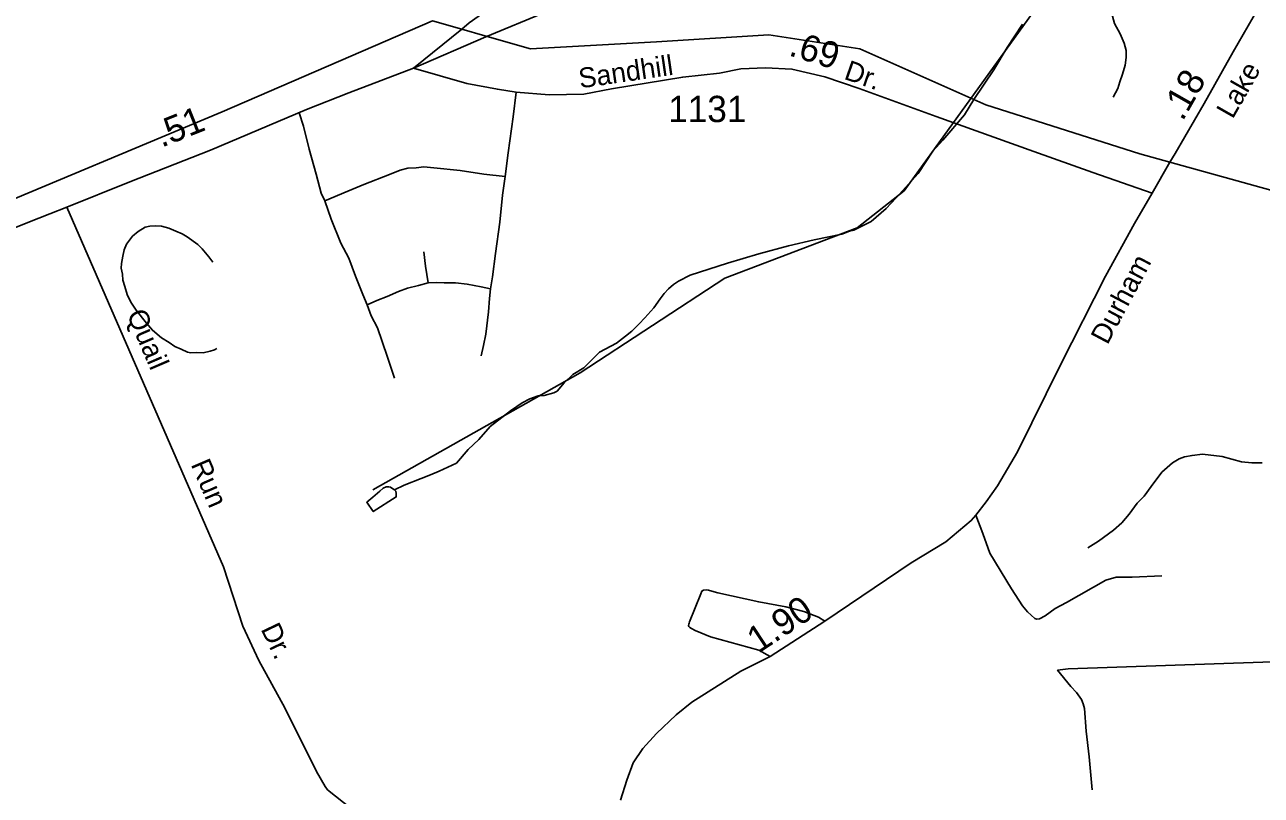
# Model space of a CAD drawing. Extents: x 2206922 to 2357709, y 510027 to 673830.
# Drawn here: x 2278661 to 2284540, y 569360 to 573022 of the extents above; entities that cross this region are included whole.
import ezdxf

# ---------------------------------------------------------------- set-up
doc = ezdxf.new("R2010")
doc.units = 0
for name, color, linetype in [('Exist Boundary Political Urban Extension UEB', 7, 'Continuous'), ('Exist Hydrographic Misc Water Feature', 7, 'Continuous'), ('Exist Road Non-System Type 51', 7, 'Continuous'), ('Exist Road Non-System Type 51 Label', 7, 'Continuous'), ('Exist Road Primary US Attributed', 7, 'Continuous'), ('Exist Road Primary US Mileage Tenths English Label', 7, 'Continuous'), ('Exist Road Secondary Mileage Hundredths English Label', 7, 'Continuous'), ('Exist Road Secondary Type 51 Attributed', 7, 'Continuous'), ('Exist Road Secondary Type 51 Label', 7, 'Continuous'), ('Exist Road Secondary Type 51 Number Label', 7, 'Continuous')]:
    doc.layers.add(name, color=color, linetype=linetype)

msp = doc.modelspace()

# ---------------------------------------------------------------- linework, layer by layer
at = {"layer": 'Exist Boundary Political Urban Extension UEB'}
msp.add_line((2280739, 573000.2), (2280848.5, 572968.9), dxfattribs=at)
for points in [[(2275447.3, 574985.8), (2276902, 573373.2), (2278101, 571907.9), (2278400.8, 572107.7), (2279599.8, 572607.2), (2280599, 573040.1), (2280739, 573000.2)], [(2280848.5, 572968.9), (2281065.3, 572906.9), (2281664.8, 572940.2), (2282197.7, 572973.5), (2282630.6, 572906.9), (2283230.1, 572640.5), (2283962.9, 572407.4), (2284105.3, 572368)], [(2284105.3, 572368), (2285528.2, 571974.5), (2286127.7, 571874.6), (2286722.8, 572028.8)]]:
    msp.add_lwpolyline(points, dxfattribs=at)
at = {"layer": 'Exist Hydrographic Misc Water Feature'}
for points in [[(2280315.7, 570810.8), (2281300.8, 571368), (2281988.8, 571816.5), (2282618.9, 572056.4), (2282841.8, 572232.2), (2283598.8, 573282.8), (2284073.7, 574119.3), (2284312.8, 574412.9), (2284475.8, 574780.2), (2284538.8, 575198.7), (2284783.8, 575692.2)], [(2280418.3, 570811.1), (2280464.6, 570833.7), (2280546.2, 570864.4), (2280589.7, 570883), (2280631.9, 570899.3), (2280713.1, 570938.2), (2280768.9, 571002.4), (2280820.4, 571051), (2280873.3, 571111.6), (2280970.7, 571186.1), (2281026.4, 571224.8), (2281062.3, 571242.9), (2281102.1, 571257.6), (2281130.2, 571259.8), (2281175.9, 571272), (2281191.7, 571280.2), (2281225.5, 571320.5), (2281267, 571358.9), (2281319.1, 571391.6), (2281393.9, 571466.2), (2281473.5, 571509), (2281517.3, 571541.3), (2281546.9, 571565.3), (2281582.3, 571599.7), (2281608.4, 571628.2), (2281651.6, 571676.4), (2281681.6, 571718.5), (2281700.9, 571744.8), (2281721.2, 571766.9), (2281744.9, 571787.3), (2281768.5, 571803.6), (2281824.3, 571832.1), (2282001.5, 571887.7), (2282150.9, 571932.9), (2282292.6, 571970.3), (2282414.4, 571999.5), (2282546.1, 572026.7), (2282582, 572040.7), (2282601.9, 572045), (2282631.8, 572059.6), (2282685.5, 572085.9), (2282756.7, 572148.6), (2282804.2, 572199.1), (2282909.2, 572313.8), (2282977.9, 572420.6), (2283025.3, 572472.7), (2283128.4, 572593.8), (2283173.5, 572666.1), (2283268.3, 572806.7), (2283331.2, 572913.3), (2283404.4, 573023.9)], [(2279554.8, 571892.6), (2279536.5, 571918.4), (2279504.5, 571956.1), (2279484.5, 571977.8), (2279433.8, 572013.4), (2279409.8, 572027.1), (2279379.9, 572041), (2279345.4, 572054.7), (2279311.4, 572064.2), (2279283.7, 572066), (2279255.2, 572063.8), (2279233.7, 572059.3), (2279199.6, 572039.3), (2279173.8, 572016.8), (2279144.1, 571978.7), (2279134.2, 571952.6), (2279127, 571922.5), (2279121.1, 571886.5), (2279119.7, 571864.4), (2279126, 571836.3), (2279128.1, 571808.4), (2279136.5, 571776.8), (2279148.4, 571738.8), (2279165, 571703.1), (2279191.4, 571665.1), (2279239.8, 571603.8), (2279268.1, 571570), (2279310.8, 571534.3), (2279346.9, 571510.7), (2279375, 571493.1), (2279405.3, 571479.1), (2279434.8, 571465.8), (2279450.8, 571461.8), (2279477.1, 571463.9), (2279509.1, 571462.3), (2279543.3, 571470.5), (2279562.6, 571476.9), (2279574.7, 571482.8)], [(2283715.5, 570536.2), (2283765.1, 570566.9), (2283836.3, 570619.4), (2283876.1, 570654), (2283911.5, 570696), (2283949.3, 570748.4), (2283983.1, 570781), (2284016.7, 570827), (2284067.6, 570895.6), (2284117.6, 570939.9), (2284149.4, 570958.2), (2284175, 570968.6), (2284210.9, 570975), (2284260.9, 570981.2), (2284353, 570970.2), (2284445.3, 570944.9), (2284494.9, 570939.5), (2284543.1, 570939.9)], [(2280418.3, 570811.1), (2280406.6, 570819.4), (2280400.2, 570823.2), (2280392.6, 570825.1), (2280386.5, 570824.8), (2280378.5, 570824.8), (2280364.7, 570818.8), (2280348.7, 570804.6), (2280315.1, 570776.4), (2280287.2, 570752.2), (2280317.8, 570708.2), (2280427.1, 570777.3), (2280427.3, 570783.4), (2280426.9, 570793.2), (2280425, 570805.2), (2280418.3, 570811.1)]]:
    msp.add_lwpolyline(points, dxfattribs=at)
at = {"layer": 'Exist Road Non-System Type 51'}
for points in [[(2283938.2, 573303.7), (2283914.6, 573276.2), (2283890.4, 573250.7), (2283868.7, 573222.6), (2283854.6, 573198.3), (2283844.4, 573166.4), (2283835.5, 573125.6), (2283834.2, 573086), (2283833, 573063), (2283842.5, 573027.9), (2283869.3, 572978.1), (2283887.2, 572933.4), (2283897.4, 572899), (2283897.4, 572865.8), (2283892.3, 572830), (2283879.5, 572786.6), (2283866.8, 572749.6), (2283857.8, 572718.9), (2283836.1, 572678.1)], [(2280945, 572300.1), (2280958.7, 572413.2), (2280982.5, 572583.4), (2280997.5, 572701.4)], [(2280087.2, 572184.4), (2280070.7, 572220.6), (2280046.8, 572311.7), (2280012.5, 572429.6), (2279985.7, 572540.1), (2279966.3, 572602.9)], [(2280087.2, 572184.4), (2280196.9, 572230.3), (2280272.7, 572262.2), (2280394.4, 572310.1), (2280446.3, 572330.1), (2280482.2, 572340.1), (2280522.1, 572342), (2280558, 572346), (2280605.9, 572342), (2280731.6, 572328.1), (2280843.3, 572312.1), (2280945, 572300.1)], [(2280945, 572300.1), (2280933, 572212.3), (2280919.1, 572082.6), (2280899.1, 571934.9), (2280885.2, 571823.1), (2280875.2, 571767.2)], [(2280289.4, 571690.6), (2280267.8, 571740.3), (2280233.8, 571826.1), (2280201.9, 571911.9), (2280164, 571983.8), (2280118.1, 572097.5), (2280087.2, 572184.4)], [(2278861.5, 572154.8), (2279606.6, 570445.9), (2279698, 570162.7), (2279774.3, 570000.8), (2279897.9, 569774.5), (2280047.8, 569473.1), (2280088.6, 569402), (2280100.5, 569386.2), (2280138.6, 569354.6), (2280458.2, 569102), (2281077.7, 568616.3), (2281222.4, 568516.3), (2281301.3, 568455.8), (2281359.2, 568429.4), (2281397.4, 568418.3)], [(2280578.9, 571794.2), (2280567, 571874), (2280559, 571941.9)], [(2280578.9, 571794.2), (2280533.1, 571782.2), (2280481.2, 571770.2), (2280437.3, 571754.2), (2280383.5, 571730.3), (2280335.6, 571710.3), (2280289.4, 571690.6)], [(2280875.2, 571767.2), (2280830.3, 571776.2), (2280764.5, 571788.2), (2280708.6, 571794.2), (2280654.8, 571794.2), (2280616.9, 571796.2), (2280578.9, 571794.2)], [(2280831.3, 571447.9), (2280841.3, 571497.8), (2280853.2, 571551.6), (2280865.2, 571657.4), (2280871.2, 571721.3), (2280875.2, 571767.2)], [(2280289.4, 571690.6), (2280307.7, 571638.5), (2280337.6, 571580.6), (2280384.5, 571445.9), (2280418.4, 571342.1)], [(2283182.2, 570691), (2283215.4, 570604.2), (2283249.2, 570510.3), (2283352.6, 570340.5), (2283404.9, 570260.1), (2283427.8, 570230.7), (2283463.6, 570200.1), (2283472.5, 570196.3), (2283485.3, 570197.5), (2283512.1, 570212.9), (2283560.5, 570247.3), (2283614, 570275.7), (2283800.4, 570381.4), (2283850.2, 570395.4), (2283925.5, 570395.4), (2284067.1, 570403.1)], [(2282205.4, 570019.8), (2282150.9, 570048.7), (2281920.9, 570112), (2281848.5, 570142.3), (2281830.3, 570151.8), (2281823, 570156.2), (2281819.2, 570160), (2281817.4, 570162.3), (2281817.2, 570166.3), (2281818.3, 570172.6), (2281819, 570177.8), (2281820.9, 570183.1), (2281874.7, 570317.4), (2281879.6, 570330.4), (2281887.4, 570334.8), (2281900, 570336.4), (2281911.9, 570334.7), (2281927.6, 570329.8), (2281955.3, 570321.1), (2282150.9, 570278.9), (2282279.8, 570254.7), (2282365.3, 570233), (2282434.2, 570206.2), (2282464.8, 570187)], [(2285749, 570033.8), (2283621, 569959.9), (2283571.1, 569953.5), (2283633.7, 569876), (2283661.9, 569848.3), (2283684.2, 569814.6), (2283692.4, 569794.7), (2283698.8, 569772.7), (2283707.8, 569664.8), (2283720.9, 569543), (2283736.3, 569385.3)]]:
    msp.add_lwpolyline(points, dxfattribs=at)
at = {"layer": 'Exist Road Primary US Attributed'}
for points in [[(2280508.6, 572815.6), (2280853.2, 572963.5), (2281419.8, 573199.4), (2282041, 573459.1), (2282204.1, 573528.5), (2282353.5, 573590.1), (2282923.1, 573815.8)], [(2278063.5, 571722.8), (2278176.7, 571803.7), (2278279.8, 571882.6), (2278369.4, 571933.5), (2278472.7, 571992.4), (2278562.4, 572035.2), (2278676.2, 572082.4), (2278780.3, 572123), (2278861.5, 572154.8), (2279159.9, 572274.9), (2279544.7, 572425.1), (2280000, 572618.5), (2280201.1, 572698.2), (2280508.6, 572815.6)]]:
    msp.add_lwpolyline(points, dxfattribs=at)
at = {"layer": 'Exist Road Secondary Type 51 Attributed'}
for points in [[(2281096.5, 573279.8), (2280925, 573136.1), (2280773.3, 573031.3), (2280739, 573000.2), (2280508.6, 572815.6)], [(2284600.4, 573232.2), (2284501.6, 573057.9), (2284405.2, 572893.3), (2284268.1, 572646.8), (2284129.6, 572410), (2284105.3, 572368), (2284020.5, 572221.7)], [(2280508.6, 572815.6), (2280763.2, 572741.7), (2280907.9, 572714.8), (2280997.5, 572701.4), (2281154.2, 572688), (2281318.3, 572692.4), (2281451.1, 572716.3), (2281789.6, 572773.2), (2281963.3, 572790.7), (2282065.1, 572811.6), (2282182.9, 572816.8), (2282308.5, 572811.2), (2282465.1, 572773.6), (2282627.8, 572718.6), (2282994.2, 572584.9), (2283457.6, 572418.4), (2283738.5, 572318.7), (2284020.5, 572221.7)], [(2284020.5, 572221.7), (2283936.9, 572076.8), (2283799.8, 571825.9), (2283585.4, 571405.9), (2283381.3, 570992.3), (2283285.6, 570830.1), (2283232, 570754.8), (2283182.2, 570691), (2283160.6, 570665.1), (2283039.3, 570564.6), (2282874.7, 570464.6), (2282464.8, 570187), (2282205.4, 570019.8), (2282065.5, 569948.8), (2281832.7, 569801.4), (2281757.8, 569742.2), (2281664.4, 569652.7), (2281599.9, 569581.7), (2281553.9, 569513.2), (2281523.6, 569431.6), (2281493.4, 569336.2)]]:
    msp.add_lwpolyline(points, dxfattribs=at)

# ---------------------------------------------------------------- texts
at = {"layer": 'Exist Road Non-System Type 51 Label'}
for s, rotation, p in [('Quail', 293.2559, (2279144.6, 571645.5)), ('Run', 293.2559, (2279449.2, 570932.2)), ('Dr.', 295.50877, (2279781.6, 570149.6))]:
    msp.add_text(s, height=95, rotation=rotation, dxfattribs=at).set_placement(p)
at = {"layer": 'Exist Road Primary US Mileage Tenths English Label'}
msp.add_text('.51', height=125, rotation=21.68344, dxfattribs=at).set_placement((2279311.4, 572437))
at = {"layer": 'Exist Road Secondary Mileage Hundredths English Label'}
for s, rotation, p in [('.69', 342.60102, (2282288.4, 572877.3)), ('.18', 60.42386, (2284165.6, 572559.4)), ('1.90', 33.58179, (2282148.7, 570031.5))]:
    msp.add_text(s, height=125, rotation=rotation, dxfattribs=at).set_placement(p)
at = {"layer": 'Exist Road Secondary Type 51 Label'}
for s, rotation, p in [('Sandhill', 8.33367, (2281301.5, 572719)), ('Dr.', 340.76444, (2282551.1, 572765.3)), ('Lake', 60.42386, (2284403.6, 572569.9)), ('Durham', 62.05207, (2283808.1, 571496.7))]:
    msp.add_text(s, height=95, rotation=rotation, dxfattribs=at).set_placement(p)
at = {"layer": 'Exist Road Secondary Type 51 Number Label'}
msp.add_text('1131', height=125, dxfattribs=at).set_placement((2281719.9, 572558.8))

doc.saveas('drawing.dxf')
